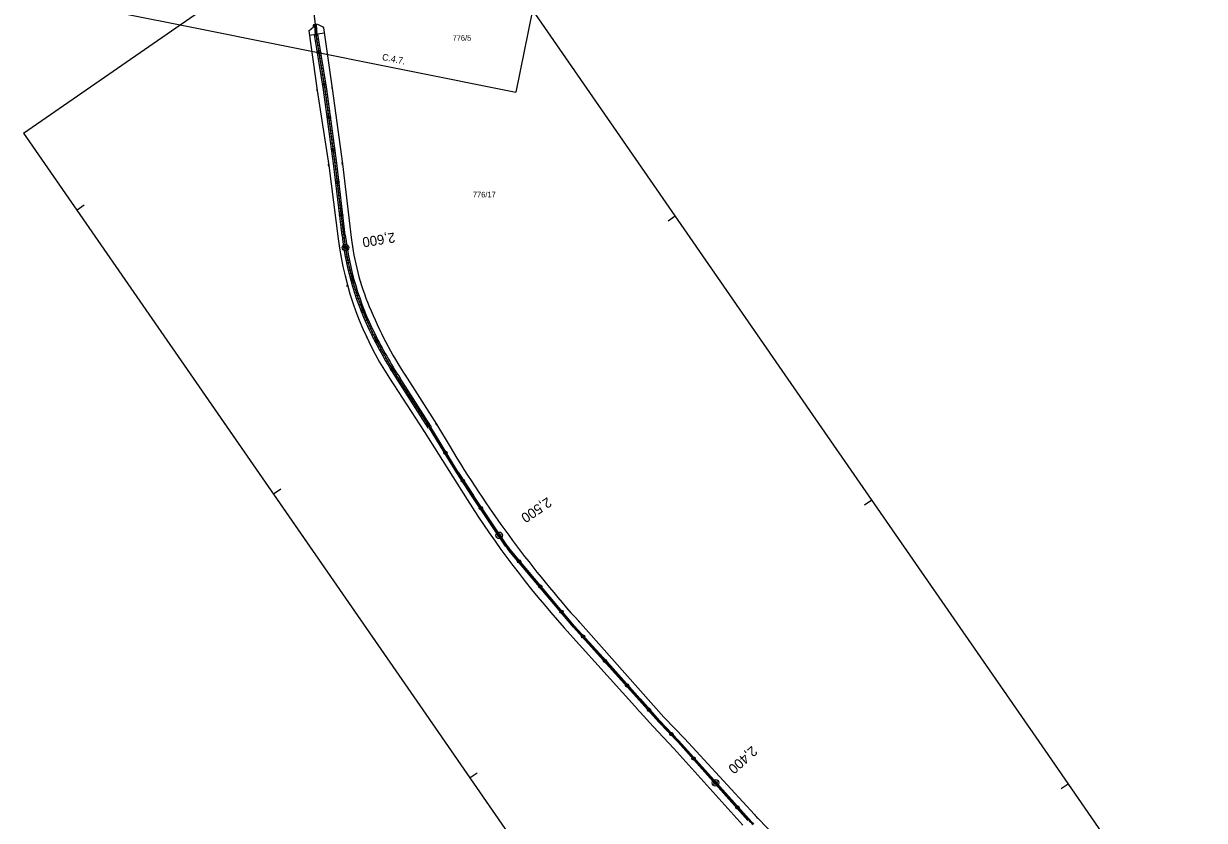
# Model space of a CAD drawing. Extents: x -548552 to -543113, y -1131925 to -1123599.
# Drawn here: x -548551.5 to -548192.5, y -1124811.6 to -1124569.3 of the extents above; entities that cross this region are included whole.
import ezdxf

# ---------------------------------------------------------------- set-up
doc = ezdxf.new("R2010")
doc.units = 0
for name, color, linetype in [('HRANY', 7, 'Continuous'), ('Parcelní čísla', 7, 'Continuous'), ('Profile', 7, 'Continuous'), ('PROFILY NÁVRH', 7, 'Continuous'), ('STANIČENÍ', 7, 'Continuous'), ('SVAHY', 7, 'Continuous')]:
    doc.layers.add(name, color=color, linetype=linetype)

msp = doc.modelspace()

# ---------------------------------------------------------------- linework, layer by layer
at = {"layer": 'HRANY'}
for p, q in [((-548463.28, -1124569.48), (-548463.02, -1124569.56)), ((-548462.87, -1124572.55), (-548462.28, -1124572.51)), ((-548462.74, -1124574.55), (-548462.15, -1124574.51)), ((-548415.15, -1124713.14), (-548419.79, -1124705.94)), ((-548419.37, -1124705.68), (-548414.74, -1124712.86))]:
    msp.add_line(p, q, dxfattribs=at)
at = {"layer": 'Profile'}
for p, q in [((-548547.45, -1124560.96), (-548503.96, -1124569.67)), ((-548396.83, -1124565.16), (-548374.89, -1124596.87)), ((-548551.52, -1124602.58), (-548503.96, -1124569.67)), ((-548374.89, -1124596.87), (-548307.99, -1124693.56)), ((-548551.52, -1124602.58), (-548430.11, -1124778.05)), ((-548533.12, -1124624.54), (-548535.29, -1124626.04)), ((-548353.43, -1124627.9), (-548355.6, -1124629.4)), ((-548497.01, -1124681.36), (-548430.11, -1124778.05)), ((-548307.99, -1124693.56), (-548241.09, -1124790.25)), ((-548473.37, -1124710.89), (-548475.54, -1124712.39)), ((-548293.68, -1124714.24), (-548295.85, -1124715.75)), ((-548430.11, -1124778.05), (-548363.21, -1124874.74)), ((-548430.11, -1124778.05), (-548363.21, -1124874.74)), ((-548241.09, -1124790.25), (-548192.53, -1124860.43)), ((-548413.63, -1124797.24), (-548415.8, -1124798.74)), ((-548233.94, -1124800.59), (-548236.11, -1124802.09))]:
    msp.add_line(p, q, dxfattribs=at)
at = {"layer": 'PROFILY NÁVRH'}
for p, q in [((-548463.41, -1124569.95), (-548463.28, -1124569.48)), ((-548463.41, -1124570.24), (-548463.41, -1124569.95)), ((-548462.52, -1124569.52), (-548463.02, -1124569.56)), ((-548463.01, -1124570.5), (-548463.02, -1124569.56)), ((-548462.52, -1124569.52), (-548462.13, -1124569.42)), ((-548462.51, -1124570.5), (-548462.52, -1124569.52)), ((-548462.13, -1124569.42), (-548460.52, -1124570.28)), ((-548464.76, -1124571.5), (-548463.41, -1124570.24)), ((-548464.76, -1124571.5), (-548462.26, -1124589.64)), ((-548460.13, -1124572.14), (-548464.57, -1124572.86)), ((-548460.34, -1124589.39), (-548463.04, -1124572.61)), ((-548462.79, -1124572.57), (-548462.88, -1124572.01)), ((-548462.3, -1124572.49), (-548462.39, -1124571.93)), ((-548459.36, -1124589.23), (-548462.05, -1124572.45)), ((-548460.52, -1124570.28), (-548460.35, -1124570.59)), ((-548460.35, -1124570.59), (-548457.71, -1124589.02)), ((-548462.26, -1124589.64), (-548458.77, -1124612.41)), ((-548457.29, -1124611.88), (-548460.35, -1124589.38)), ((-548456.29, -1124611.74), (-548459.35, -1124589.24)), ((-548457.71, -1124589.02), (-548454.62, -1124611.92)), ((-548458.77, -1124612.41), (-548455.9, -1124634.79)), ((-548454.71, -1124633.72), (-548457.29, -1124611.87)), ((-548453.72, -1124633.6), (-548456.29, -1124611.75)), ((-548454.62, -1124611.92), (-548451.93, -1124634.37)), ((-548440.31, -1124677.14), (-548429.76, -1124693.32)), ((-548428.51, -1124692.25), (-548437.9, -1124677.67)), ((-548427.67, -1124691.71), (-548437.06, -1124677.13)), ((-548435.67, -1124676.03), (-548425.97, -1124691.12)), ((-548419.37, -1124705.68), (-548427.74, -1124692.08)), ((-548427.52, -1124691.94), (-548427.66, -1124691.72)), ((-548425.97, -1124691.12), (-548421.86, -1124698.01)), ((-548429.76, -1124693.32), (-548416.72, -1124713.99)), ((-548428.38, -1124692.47), (-548428.52, -1124692.24)), ((-548419.79, -1124705.94), (-548428.16, -1124692.34)), ((-548404.99, -1124728.23), (-548415.15, -1124713.14)), ((-548404.58, -1124727.95), (-548414.74, -1124712.86)), ((-548384.39, -1124752.84), (-548404.01, -1124729.52)), ((-548384.01, -1124752.52), (-548403.63, -1124729.2)), ((-548364.75, -1124777.89), (-548387.15, -1124753.03)), ((-548373.5, -1124764.91), (-548384.39, -1124752.84)), ((-548373.13, -1124764.57), (-548384.01, -1124752.52)), ((-548383.78, -1124749.96), (-548356.89, -1124780.23)), ((-548364.4, -1124775.03), (-548373.5, -1124764.9)), ((-548364.03, -1124774.7), (-548373.13, -1124764.57)), ((-548358.05, -1124781.4), (-548364.02, -1124774.7)), ((-548364.75, -1124777.89), (-548364.67, -1124778.13)), ((-548364.67, -1124778.13), (-548364.05, -1124778.67)), ((-548358.43, -1124781.74), (-548364.4, -1124775.03)), ((-548360.09, -1124783.07), (-548364.05, -1124778.67)), ((-548352.65, -1124787.76), (-548358.42, -1124781.74)), ((-548352.29, -1124787.42), (-548358.06, -1124781.4)), ((-548356.89, -1124780.23), (-548350.5, -1124786.84)), ((-548360.09, -1124783.07), (-548353.8, -1124789.79)), ((-548331.3, -1124811.64), (-548352.66, -1124787.76)), ((-548330.93, -1124811.31), (-548352.28, -1124787.42)), ((-548350.6, -1124786.73), (-548329.34, -1124809.89)), ((-548353.8, -1124789.79), (-548332.83, -1124813.13)), ((-548328.32, -1124810.98), (-548306.7, -1124833.03))]:
    msp.add_line(p, q, dxfattribs=at)
msp.add_circle((-548384.12, -1124752.77), 0.1, dxfattribs=at)
for centre, radius, start, end in [((-548373.12, -1124624.93), 79.38, 186.8289, 202.4816), ((-548355.5, -1124621.88), 101.22, 187.3268, 213.0854), ((-548322.5, -1124603.99), 134.16, 202.4816, 212.74), ((-548126.73, -1124521.63), 343.82, 210.8651, 221.6156), ((-548172.58, -1124559.8), 288.75, 212.2745, 222.0043)]:
    msp.add_arc(centre, radius, start, end, dxfattribs=at)
for centre, major_axis, ratio, start_param, end_param in [((-548452.77, -1124570.39), (4.28, -9.31), 0.999251, 4.292048, 4.440187), ((-548452.77, -1124570.39), (4.08, -8.86), 0.999212, 4.292048, 4.440187), ((-548363.24, -1124622.94), (51.28, -76.52), 0.999934, 4.239319, 4.584526), ((-548363.24, -1124622.94), (50.72, -75.69), 0.999933, 4.239319, 4.584526), ((-548317.78, -1124600.27), (79.56, -118.72), 0.999934, 4.584526, 4.694368), ((-548317.78, -1124600.27), (79, -117.89), 0.999933, 4.584526, 4.694368), ((-548392.34, -1124719.71), (-4.95, -13.89), 0.999992, 5.647365, 5.754146), ((-548392.34, -1124719.71), (-5.12, -14.37), 0.999992, 5.647365, 5.754146), ((-548305.06, -1124788.18), (21.6, -24.45), 0.998598, 4.718307, 4.764313), ((-548305.06, -1124788.18), (23.01, -26.04), 0.998684, 4.718307, 4.775378)]:
    msp.add_ellipse(centre, major_axis=major_axis, ratio=ratio, start_param=start_param, end_param=end_param, dxfattribs=at)
at = {"layer": 'STANIČENÍ'}
for p, q in [((-548462.77, -1124569.54), (-548463.56, -1124562.85)), ((-548462.76, -1124570.5), (-548462.77, -1124569.54)), ((-548459.85, -1124589.31), (-548462.63, -1124571.97)), ((-548462.25, -1124589.7), (-548462.31, -1124589.32)), ((-548456.79, -1124611.81), (-548459.85, -1124589.31)), ((-548457.71, -1124589.02), (-548457.75, -1124588.75)), ((-548458.74, -1124612.7), (-548458.82, -1124612.05)), ((-548454.21, -1124633.66), (-548456.79, -1124611.81)), ((-548454.58, -1124612.3), (-548454.66, -1124611.56)), ((-548428.09, -1124691.98), (-548437.48, -1124677.4)), ((-548419.58, -1124705.81), (-548428.09, -1124691.98)), ((-548425.85, -1124691.34), (-548426.17, -1124690.8)), ((-548429.67, -1124693.47), (-548429.9, -1124693.1)), ((-548404.78, -1124728.09), (-548414.94, -1124713)), ((-548384.2, -1124752.68), (-548403.82, -1124729.36)), ((-548373.31, -1124764.74), (-548384.2, -1124752.68)), ((-548382.58, -1124751.32), (-548382.76, -1124751.1)), ((-548386, -1124754.3), (-548386.13, -1124754.14)), ((-548364.21, -1124774.86), (-548373.31, -1124764.74)), ((-548358.24, -1124781.57), (-548364.21, -1124774.86)), ((-548352.47, -1124787.59), (-548358.24, -1124781.57)), ((-548356.82, -1124780.31), (-548356.96, -1124780.15)), ((-548360.02, -1124783.15), (-548360.21, -1124782.94)), ((-548331.12, -1124811.47), (-548352.47, -1124787.59)), ((-548350.19, -1124787.18), (-548351, -1124786.28)), ((-548353.52, -1124790.11), (-548354.3, -1124789.23))]:
    msp.add_line(p, q, dxfattribs=at)
for centre, radius in [((-548462.76, -1124570.04), 0.1), ((-548462.74, -1124571.04), 0.1), ((-548462.62, -1124572.03), 0.1), ((-548462.47, -1124573.02), 0.1), ((-548462.31, -1124574.01), 0.1), ((-548462.15, -1124575), 0.1), ((-548461.99, -1124575.98), 0.1), ((-548461.83, -1124576.97), 0.1), ((-548461.67, -1124577.96), 0.5), ((-548461.67, -1124577.96), 0.1), ((-548461.51, -1124578.95), 0.1), ((-548461.36, -1124579.93), 0.1), ((-548461.2, -1124580.92), 0.1), ((-548461.04, -1124581.91), 0.1), ((-548460.88, -1124582.89), 0.1), ((-548460.72, -1124583.88), 0.1), ((-548460.56, -1124584.87), 0.1), ((-548460.09, -1124587.83), 0.5), ((-548460.4, -1124585.86), 0.1), ((-548460.25, -1124586.84), 0.1), ((-548460.09, -1124587.83), 0.1), ((-548459.93, -1124588.82), 0.1), ((-548459.78, -1124589.81), 0.1), ((-548459.65, -1124590.8), 0.1), ((-548459.51, -1124591.79), 0.1), ((-548459.38, -1124592.78), 0.1), ((-548459.24, -1124593.77), 0.1), ((-548459.11, -1124594.76), 0.1), ((-548458.7, -1124597.73), 0.5), ((-548458.97, -1124595.75), 0.1), ((-548458.84, -1124596.74), 0.1), ((-548458.7, -1124597.73), 0.1), ((-548458.57, -1124598.73), 0.1), ((-548458.43, -1124599.72), 0.1), ((-548458.3, -1124600.71), 0.1), ((-548458.17, -1124601.7), 0.1), ((-548458.03, -1124602.69), 0.1), ((-548457.9, -1124603.68), 0.1), ((-548457.76, -1124604.67), 0.1), ((-548457.63, -1124605.66), 0.1), ((-548457.36, -1124607.64), 0.5), ((-548457.49, -1124606.65), 0.1), ((-548457.36, -1124607.64), 0.1), ((-548457.22, -1124608.63), 0.1), ((-548457.09, -1124609.62), 0.1), ((-548456.95, -1124610.62), 0.1), ((-548456.82, -1124611.61), 0.1), ((-548456.7, -1124612.6), 0.1), ((-548456.58, -1124613.59), 0.1), ((-548456.46, -1124614.59), 0.1), ((-548456.35, -1124615.58), 0.1), ((-548456.23, -1124616.57), 0.1), ((-548456.11, -1124617.56), 0.5), ((-548456.11, -1124617.56), 0.1), ((-548455.99, -1124618.56), 0.1), ((-548455.88, -1124619.55), 0.1), ((-548455.76, -1124620.54), 0.1), ((-548455.64, -1124621.54), 0.1), ((-548455.53, -1124622.53), 0.1), ((-548455.41, -1124623.52), 0.1), ((-548454.94, -1124627.5), 0.5), ((-548455.29, -1124624.52), 0.1), ((-548455.17, -1124625.51), 0.1), ((-548455.06, -1124626.5), 0.1), ((-548454.94, -1124627.5), 0.1), ((-548454.82, -1124628.49), 0.1), ((-548454.71, -1124629.48), 0.1), ((-548454.59, -1124630.48), 0.1), ((-548454.47, -1124631.47), 0.1), ((-548454.36, -1124632.46), 0.1), ((-548454.24, -1124633.45), 0.1), ((-548454.12, -1124634.45), 0.1), ((-548453.69, -1124637.42), 1), ((-548453.69, -1124637.42), 0.5), ((-548453.99, -1124635.44), 0.1), ((-548453.84, -1124636.43), 0.1), ((-548453.69, -1124637.42), 0.1), ((-548453.53, -1124638.4), 0.1), ((-548453.35, -1124639.39), 0.1), ((-548453.24, -1124639.98), 0.1), ((-548453.17, -1124640.37), 0.1), ((-548453.05, -1124640.96), 0.1), ((-548452.97, -1124641.35), 0.1), ((-548452.85, -1124641.94), 0.1), ((-548452.77, -1124642.33), 0.1), ((-548452.55, -1124643.31), 0.1), ((-548452.32, -1124644.28), 0.1), ((-548452.08, -1124645.25), 0.1), ((-548451.58, -1124647.19), 0.5), ((-548451.84, -1124646.22), 0.1), ((-548451.58, -1124647.19), 0.1), ((-548451.31, -1124648.15), 0.1), ((-548451.03, -1124649.11), 0.1), ((-548450.73, -1124650.06), 0.1), ((-548450.43, -1124651.02), 0.1), ((-548450.12, -1124651.97), 0.1), ((-548449.8, -1124652.91), 0.1), ((-548449.47, -1124653.86), 0.1), ((-548449.12, -1124654.8), 0.1), ((-548448.41, -1124656.66), 0.5), ((-548448.77, -1124655.73), 0.1), ((-548448.41, -1124656.66), 0.1), ((-548448.03, -1124657.59), 0.1), ((-548447.65, -1124658.52), 0.1), ((-548447.26, -1124659.44), 0.1), ((-548446.85, -1124660.35), 0.1), ((-548446.44, -1124661.26), 0.1), ((-548446.02, -1124662.17), 0.1), ((-548445.58, -1124663.07), 0.1), ((-548445.14, -1124663.96), 0.1), ((-548444.69, -1124664.86), 0.1), ((-548444.23, -1124665.75), 0.5), ((-548444.23, -1124665.75), 0.1), ((-548443.77, -1124666.63), 0.1), ((-548443.3, -1124667.52), 0.1), ((-548442.83, -1124668.4), 0.1), ((-548442.35, -1124669.27), 0.1), ((-548441.86, -1124670.15), 0.1), ((-548441.36, -1124671.02), 0.1), ((-548440.86, -1124671.88), 0.1), ((-548440.36, -1124672.74), 0.1), ((-548439.85, -1124673.6), 0.1), ((-548439.33, -1124674.46), 0.5), ((-548439.33, -1124674.46), 0.1), ((-548438.8, -1124675.31), 0.1), ((-548438.27, -1124676.16), 0.1), ((-548437.74, -1124677), 0.1), ((-548437.2, -1124677.84), 0.1), ((-548436.66, -1124678.68), 0.1), ((-548436.11, -1124679.53), 0.1), ((-548435.57, -1124680.37), 0.1), ((-548435.03, -1124681.21), 0.1), ((-548434.49, -1124682.05), 0.1), ((-548433.95, -1124682.89), 0.5), ((-548433.95, -1124682.89), 0.1), ((-548433.41, -1124683.73), 0.1), ((-548432.87, -1124684.57), 0.1), ((-548432.32, -1124685.41), 0.1), ((-548431.78, -1124686.25), 0.1), ((-548431.24, -1124687.09), 0.1), ((-548430.7, -1124687.93), 0.1), ((-548430.16, -1124688.77), 0.1), ((-548429.62, -1124689.61), 0.1), ((-548429.07, -1124690.45), 0.1), ((-548428.53, -1124691.29), 0.5), ((-548428.53, -1124691.29), 0.1), ((-548427.99, -1124692.14), 0.1), ((-548427.47, -1124692.99), 0.1), ((-548426.95, -1124693.84), 0.1), ((-548426.42, -1124694.69), 0.1), ((-548425.9, -1124695.54), 0.1), ((-548425.37, -1124696.4), 0.1), ((-548424.85, -1124697.25), 0.1), ((-548424.33, -1124698.1), 0.1), ((-548423.8, -1124698.95), 0.1), ((-548423.28, -1124699.8), 0.5), ((-548423.28, -1124699.8), 0.1), ((-548422.75, -1124700.65), 0.1), ((-548422.23, -1124701.51), 0.1), ((-548421.71, -1124702.36), 0.1), ((-548421.18, -1124703.21), 0.1), ((-548420.66, -1124704.06), 0.1), ((-548420.13, -1124704.91), 0.1), ((-548419.61, -1124705.76), 0.1), ((-548419.08, -1124706.61), 0.1), ((-548418.55, -1124707.46), 0.1), ((-548418.02, -1124708.31), 0.5), ((-548418.02, -1124708.31), 0.1), ((-548417.48, -1124709.15), 0.1), ((-548416.94, -1124709.99), 0.1), ((-548416.39, -1124710.83), 0.1), ((-548415.84, -1124711.66), 0.1), ((-548415.29, -1124712.49), 0.1), ((-548414.73, -1124713.32), 0.1), ((-548414.17, -1124714.15), 0.1), ((-548413.61, -1124714.98), 0.1), ((-548413.05, -1124715.81), 0.1), ((-548412.49, -1124716.64), 0.5), ((-548412.49, -1124716.64), 0.1), ((-548411.93, -1124717.47), 0.1), ((-548411.38, -1124718.3), 0.1), ((-548410.82, -1124719.13), 0.1), ((-548410.26, -1124719.96), 0.1), ((-548409.7, -1124720.79), 0.1), ((-548409.14, -1124721.62), 0.1), ((-548408.58, -1124722.45), 0.1), ((-548408.02, -1124723.28), 0.1), ((-548406.91, -1124724.93), 1), ((-548407.46, -1124724.11), 0.1), ((-548406.91, -1124724.93), 0.5), ((-548406.91, -1124724.93), 0.1), ((-548406.35, -1124725.76), 0.1), ((-548405.79, -1124726.59), 0.1), ((-548405.23, -1124727.42), 0.1), ((-548404.67, -1124728.25), 0.1), ((-548404.07, -1124729.05), 0.1), ((-548403.43, -1124729.82), 0.1), ((-548402.79, -1124730.59), 0.1), ((-548402.15, -1124731.35), 0.1), ((-548401.5, -1124732.12), 0.1), ((-548400.86, -1124732.88), 0.5), ((-548400.86, -1124732.88), 0.1), ((-548400.21, -1124733.65), 0.1), ((-548399.57, -1124734.41), 0.1), ((-548398.93, -1124735.18), 0.1), ((-548398.28, -1124735.94), 0.1), ((-548397.64, -1124736.71), 0.1), ((-548397, -1124737.47), 0.1), ((-548396.35, -1124738.24), 0.1), ((-548395.71, -1124739), 0.1), ((-548395.06, -1124739.77), 0.1), ((-548394.42, -1124740.53), 0.5), ((-548394.42, -1124740.53), 0.1), ((-548393.78, -1124741.3), 0.1), ((-548393.13, -1124742.06), 0.1), ((-548392.49, -1124742.83), 0.1), ((-548391.84, -1124743.6), 0.1), ((-548391.2, -1124744.36), 0.1), ((-548390.56, -1124745.13), 0.1), ((-548389.91, -1124745.89), 0.1), ((-548389.27, -1124746.66), 0.1), ((-548388.63, -1124747.42), 0.1), ((-548387.98, -1124748.19), 0.5), ((-548387.98, -1124748.19), 0.1), ((-548387.34, -1124748.95), 0.1), ((-548386.69, -1124749.72), 0.1), ((-548386.05, -1124750.48), 0.1), ((-548385.41, -1124751.25), 0.1), ((-548384.76, -1124752.01), 0.1), ((-548383.44, -1124753.52), 0.1), ((-548382.77, -1124754.26), 0.1), ((-548382.1, -1124755), 0.1), ((-548381.43, -1124755.74), 0.5), ((-548381.43, -1124755.74), 0.1), ((-548380.76, -1124756.48), 0.1), ((-548380.09, -1124757.23), 0.1), ((-548379.42, -1124757.97), 0.1), ((-548378.75, -1124758.71), 0.1), ((-548378.08, -1124759.45), 0.1), ((-548377.41, -1124760.2), 0.1), ((-548376.74, -1124760.94), 0.1), ((-548376.07, -1124761.68), 0.1), ((-548375.4, -1124762.42), 0.1), ((-548374.73, -1124763.16), 0.5), ((-548374.73, -1124763.16), 0.1), ((-548374.06, -1124763.91), 0.1), ((-548373.39, -1124764.65), 0.1), ((-548372.72, -1124765.39), 0.1), ((-548372.05, -1124766.14), 0.1), ((-548371.39, -1124766.88), 0.1), ((-548370.72, -1124767.62), 0.1), ((-548370.05, -1124768.37), 0.1), ((-548369.38, -1124769.11), 0.1), ((-548368.71, -1124769.86), 0.1), ((-548368.04, -1124770.6), 0.5), ((-548368.04, -1124770.6), 0.1), ((-548367.38, -1124771.34), 0.1), ((-548366.71, -1124772.09), 0.1), ((-548366.04, -1124772.83), 0.1), ((-548365.37, -1124773.57), 0.1), ((-548364.7, -1124774.32), 0.1), ((-548364.04, -1124775.06), 0.1), ((-548363.37, -1124775.81), 0.1), ((-548362.71, -1124776.56), 0.1), ((-548362.04, -1124777.3), 0.1), ((-548361.38, -1124778.05), 0.5), ((-548361.38, -1124778.05), 0.1), ((-548360.71, -1124778.8), 0.1), ((-548360.05, -1124779.54), 0.1), ((-548359.38, -1124780.29), 0.1), ((-548358.72, -1124781.04), 0.1), ((-548358.04, -1124781.78), 0.1), ((-548357.35, -1124782.5), 0.1), ((-548356.66, -1124783.22), 0.1), ((-548355.97, -1124783.94), 0.1), ((-548355.28, -1124784.66), 0.1), ((-548354.58, -1124785.39), 0.5), ((-548354.58, -1124785.39), 0.1), ((-548353.89, -1124786.11), 0.1), ((-548353.2, -1124786.83), 0.1), ((-548352.51, -1124787.55), 0.1), ((-548351.84, -1124788.29), 0.1), ((-548351.17, -1124789.04), 0.1), ((-548350.51, -1124789.79), 0.1), ((-548349.84, -1124790.53), 0.1), ((-548349.17, -1124791.28), 0.1), ((-548348.51, -1124792.02), 0.1), ((-548347.84, -1124792.77), 0.5), ((-548347.84, -1124792.77), 0.1), ((-548347.17, -1124793.51), 0.1), ((-548346.51, -1124794.26), 0.1), ((-548345.84, -1124795), 0.1), ((-548345.18, -1124795.75), 0.1), ((-548344.51, -1124796.5), 0.1), ((-548343.84, -1124797.24), 0.1), ((-548343.18, -1124797.99), 0.1), ((-548342.51, -1124798.73), 0.1), ((-548341.18, -1124800.22), 1), ((-548341.84, -1124799.48), 0.1), ((-548341.18, -1124800.22), 0.5), ((-548341.18, -1124800.22), 0.1), ((-548340.51, -1124800.97), 0.1), ((-548339.84, -1124801.71), 0.1), ((-548339.18, -1124802.46), 0.1), ((-548338.51, -1124803.2), 0.1), ((-548337.84, -1124803.95), 0.1), ((-548337.18, -1124804.7), 0.1), ((-548336.51, -1124805.44), 0.1), ((-548335.84, -1124806.19), 0.1), ((-548335.18, -1124806.93), 0.1), ((-548334.51, -1124807.68), 0.5), ((-548334.51, -1124807.68), 0.1), ((-548333.84, -1124808.42), 0.1), ((-548333.18, -1124809.17), 0.1), ((-548332.51, -1124809.91), 0.1), ((-548331.85, -1124810.66), 0.1), ((-548331.18, -1124811.41), 0.1)]:
    msp.add_circle(centre, radius, dxfattribs=at)
for centre, major_axis, ratio, start_param, end_param in [((-548452.77, -1124570.39), (4.18, -9.08), 0.999232, 4.292048, 4.440187), ((-548363.24, -1124622.94), (52.01, -77.61), 0.999935, 4.239319, 4.243155), ((-548363.24, -1124622.94), (51, -76.1), 0.999933, 4.239319, 4.584526), ((-548363.24, -1124622.94), (49.79, -74.29), 0.999932, 4.239319, 4.243531), ((-548363.24, -1124622.94), (52.15, -77.82), 0.999935, 4.402107, 4.406365), ((-548363.24, -1124622.94), (49.79, -74.29), 0.999932, 4.401323, 4.40527), ((-548363.24, -1124622.94), (49.68, -74.14), 0.999932, 4.580922, 4.584526), ((-548363.24, -1124622.94), (52.23, -77.95), 0.999935, 4.580512, 4.584526), ((-548363.24, -1124622.94), (52.23, -77.95), 0.999935, 4.580904, 4.584526), ((-548317.78, -1124600.27), (79.28, -118.3), 0.999933, 4.584526, 4.694368), ((-548317.78, -1124600.27), (80.52, -120.16), 0.999934, 4.687881, 4.690702), ((-548317.78, -1124600.27), (78.02, -116.43), 0.999932, 4.688262, 4.690661), ((-548249.24, -1124601.02), (50.03, -193.64), 0.999954, 5.011051, 5.053828), ((-548249.24, -1124601.02), (50.52, -195.52), 0.999955, 5.032682, 5.034953), ((-548392.34, -1124719.71), (-5.03, -14.13), 0.999992, 5.647365, 5.754146), ((-548392.34, -1124719.71), (-4.19, -11.76), 0.99999, 5.682163, 5.718313), ((-548392.34, -1124719.71), (-5.69, -15.99), 0.999993, 5.69232, 5.713494), ((-548305.06, -1124788.18), (23.17, -26.23), 0.998693, 4.718307, 4.775378)]:
    msp.add_ellipse(centre, major_axis=major_axis, ratio=ratio, start_param=start_param, end_param=end_param, dxfattribs=at)
at = {"layer": 'SVAHY'}
for p, q in [((-548503.96, -1124569.67), (-548429.41, -1124518.08)), ((-548396.83, -1124565.16), (-548401.84, -1124590.14)), ((-548503.96, -1124569.67), (-548401.84, -1124590.14))]:
    msp.add_line(p, q, dxfattribs=at)

# ---------------------------------------------------------------- texts
at = {"layer": 'Parcelní čísla'}
for s, p in [('776/5', (-548421.12, -1124574.5)), ('776/17', (-548414.94, -1124622.15))]:
    msp.add_text(s, height=1.7, dxfattribs=at).set_placement(p)
at = {"layer": 'Profile'}
msp.add_text('C.4.7.', height=2, rotation=348.6654, dxfattribs=at).set_placement((-548442.67, -1124580.34))
at = {"layer": 'STANIČENÍ'}
for s, rotation, p in [('2,600', 189.0782, (-548438.81, -1124632.81)), ('2,500', 213.9615, (-548392.26, -1124713.23)), ('2,400', 221.7971, (-548330.08, -1124788.83))]:
    msp.add_text(s, height=3, rotation=rotation, dxfattribs=at).set_placement(p)

doc.saveas('drawing.dxf')
